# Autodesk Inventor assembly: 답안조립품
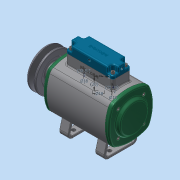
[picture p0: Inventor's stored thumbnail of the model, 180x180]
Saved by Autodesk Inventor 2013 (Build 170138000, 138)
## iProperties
Created: 2016-10
Part Number: 답안조립품
Document SubType Name: Assembly
Designer: user
Mass: 2472.7 g
Surface Area: 2685.93 cm^2
Volume: 918.558 cm^3
Density: 2.69193 g/cm^3
Author: user
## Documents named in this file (18)
- C:\Users\user\Desktop\361008V1005\답안조립품.iam
- C:\Users\user\Desktop\361008V1005\본체.ipt
- C:\Users\user\Desktop\361008V1005\베어링 6203.ipt
- C:\Users\user\Desktop\361008V1005\앞커버.ipt
- C:\Users\user\Desktop\361008V1005\축.ipt
- C:\Users\user\Desktop\361008V1005\키 - 5 x 5 x 18.ipt
- C:\Users\user\Desktop\361008V1005\오일실 17 30 8.ipt
- C:\Users\user\Desktop\361008V1005\부시.ipt
- C:\Users\user\Desktop\361008V1005\슬라이드.ipt
- C:\Users\user\Desktop\361008V1005\스프링1.ipt
- C:\Users\user\Desktop\361008V1005\스프링2.ipt
- C:\Users\user\Desktop\361008V1005\스프링3.ipt
- C:\Users\user\Desktop\361008V1005\뒷커버.ipt
- C:\Users\user\Desktop\361008V1005\헤더커버.ipt
- C:\Users\user\Desktop\361008V1005\V-벨트풀리.ipt
- C:\Users\user\Desktop\361008V1005\멈춤나사 M4x5.ipt
- C:\Users\user\Desktop\361008V1005\볼트 M4 x 12.ipt
- C:\Users\user\Desktop\361008V1005\볼트 M4 x 16.ipt
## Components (4 placed, 3 different names)
1. 7-베어링 6203:1
2. 7-베어링 6203:2
3. 헤더커버:1
4. V-벨트풀리:1
